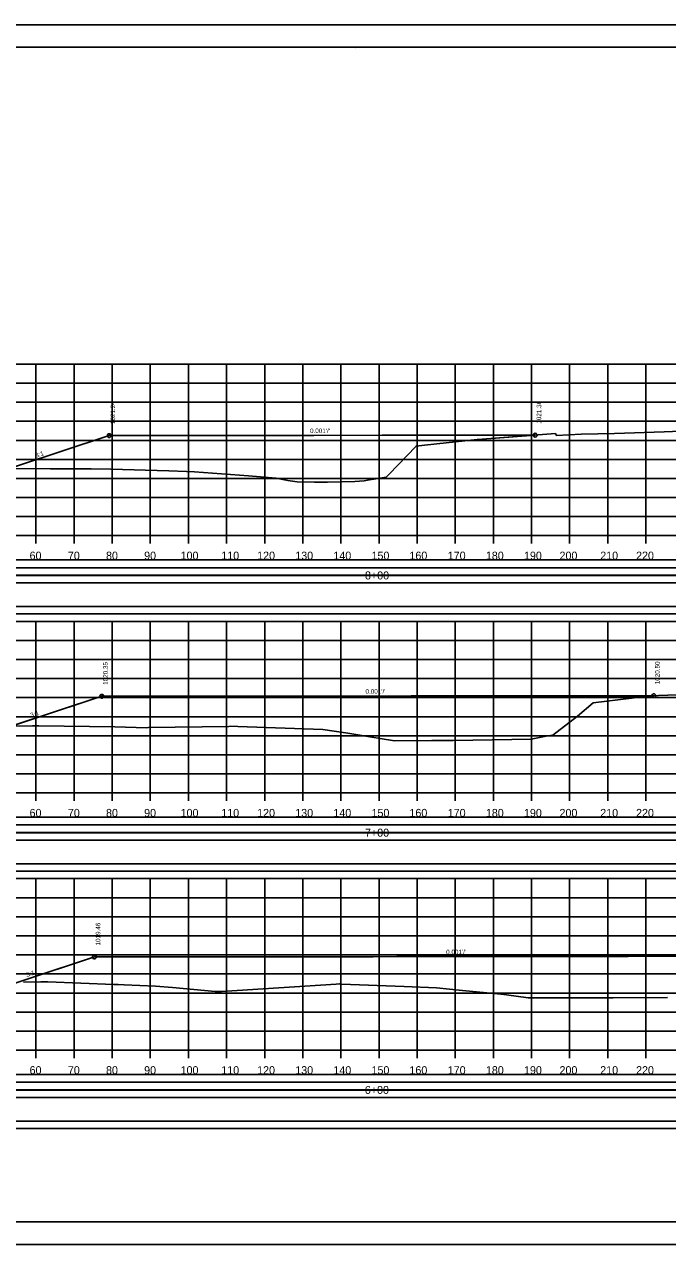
# Model space of a CAD drawing. Extents: x 1370565 to 1374448, y 301010 to 304637.
# Drawn here: x 1374108.6 to 1374277.1, y 301728.1 to 302053 of the extents above; entities that cross this region are included whole.
import ezdxf

# ---------------------------------------------------------------- set-up
doc = ezdxf.new("R2010")
doc.units = 0
for name, color, linetype in [('Default', 7, 'Continuous'), ('R_Axis', 7, 'Continuous'), ('R_Axis Annot', 7, 'Continuous'), ('R_Border', 7, 'Continuous'), ('R_Contours', 7, 'Continuous'), ('R_Drive', 7, 'Continuous'), ('R_Exist Surface', 7, 'Continuous'), ('R_Fin Surface', 7, 'Continuous'), ('R_Grid', 7, 'Continuous'), ('R_No Plot', 7, 'Continuous'), ('R_Xsect Elev', 7, 'Continuous'), ('R_Xsect Slope', 7, 'Continuous')]:
    doc.layers.add(name, color=color, linetype=linetype)

msp = doc.modelspace()

# ---------------------------------------------------------------- linework, layer by layer
at = {"layer": 'Default'}
for points in [[(1373981.44, 301908.59), (1374421.61, 301908.59), (1374421.61, 301912.58), (1373981.44, 301912.58)], [(1373981.44, 301900.36), (1374421.61, 301900.36), (1374421.61, 301908.51), (1373981.44, 301908.51)], [(1373981.44, 301841.09), (1374421.61, 301841.09), (1374421.61, 301845.08), (1373981.44, 301845.08)], [(1373981.44, 301832.86), (1374421.61, 301832.86), (1374421.61, 301841.01), (1373981.44, 301841.01)], [(1373981.44, 301773.59), (1374421.61, 301773.59), (1374421.61, 301777.58), (1373981.44, 301777.58)], [(1373981.44, 301765.36), (1374421.61, 301765.36), (1374421.61, 301773.51), (1373981.44, 301773.51)]]:
    msp.add_lwpolyline(points, close=True, dxfattribs=at)
at = {"layer": 'R_Axis'}
for p, q in [((1373981.52, 301918.96), (1374421.52, 301918.96)), ((1374111.52, 301916.86), (1374111.52, 301918.96)), ((1374121.52, 301916.86), (1374121.52, 301918.96)), ((1374131.52, 301916.86), (1374131.52, 301918.96)), ((1374141.52, 301916.86), (1374141.52, 301918.96)), ((1374151.52, 301916.86), (1374151.52, 301918.96)), ((1374161.52, 301916.86), (1374161.52, 301918.96)), ((1374171.52, 301916.86), (1374171.52, 301918.96)), ((1374181.52, 301916.86), (1374181.52, 301918.96)), ((1374191.52, 301916.86), (1374191.52, 301918.96)), ((1374201.52, 301916.86), (1374201.52, 301918.96)), ((1374211.52, 301916.86), (1374211.52, 301918.96)), ((1374221.52, 301916.86), (1374221.52, 301918.96)), ((1374231.52, 301916.86), (1374231.52, 301918.96)), ((1374241.52, 301916.86), (1374241.52, 301918.96)), ((1374251.52, 301916.86), (1374251.52, 301918.96)), ((1374261.52, 301916.86), (1374261.52, 301918.96)), ((1374271.52, 301916.86), (1374271.52, 301918.96)), ((1373981.52, 301851.46), (1374421.52, 301851.46)), ((1374111.52, 301849.36), (1374111.52, 301851.46)), ((1374121.52, 301849.36), (1374121.52, 301851.46)), ((1374131.52, 301849.36), (1374131.52, 301851.46)), ((1374141.52, 301849.36), (1374141.52, 301851.46)), ((1374151.52, 301849.36), (1374151.52, 301851.46)), ((1374161.52, 301849.36), (1374161.52, 301851.46)), ((1374171.52, 301849.36), (1374171.52, 301851.46)), ((1374181.52, 301849.36), (1374181.52, 301851.46)), ((1374191.52, 301849.36), (1374191.52, 301851.46)), ((1374201.52, 301849.36), (1374201.52, 301851.46)), ((1374211.52, 301849.36), (1374211.52, 301851.46)), ((1374221.52, 301849.36), (1374221.52, 301851.46)), ((1374231.52, 301849.36), (1374231.52, 301851.46)), ((1374241.52, 301849.36), (1374241.52, 301851.46)), ((1374251.52, 301849.36), (1374251.52, 301851.46)), ((1374261.52, 301849.36), (1374261.52, 301851.46)), ((1374271.52, 301849.36), (1374271.52, 301851.46)), ((1373981.52, 301783.96), (1374421.52, 301783.96)), ((1374111.52, 301781.86), (1374111.52, 301783.96)), ((1374121.52, 301781.86), (1374121.52, 301783.96)), ((1374131.52, 301781.86), (1374131.52, 301783.96)), ((1374141.52, 301781.86), (1374141.52, 301783.96)), ((1374151.52, 301781.86), (1374151.52, 301783.96)), ((1374161.52, 301781.86), (1374161.52, 301783.96)), ((1374171.52, 301781.86), (1374171.52, 301783.96)), ((1374181.52, 301781.86), (1374181.52, 301783.96)), ((1374191.52, 301781.86), (1374191.52, 301783.96)), ((1374201.52, 301781.86), (1374201.52, 301783.96)), ((1374211.52, 301781.86), (1374211.52, 301783.96)), ((1374221.52, 301781.86), (1374221.52, 301783.96)), ((1374231.52, 301781.86), (1374231.52, 301783.96)), ((1374241.52, 301781.86), (1374241.52, 301783.96)), ((1374251.52, 301781.86), (1374251.52, 301783.96)), ((1374261.52, 301781.86), (1374261.52, 301783.96)), ((1374271.52, 301781.86), (1374271.52, 301783.96))]:
    msp.add_line(p, q, dxfattribs=at)
at = {"layer": 'R_Border'}
for p, q in [((1373966.52, 302047.15), (1374440.79, 302047.15)), ((1374195.3, 302046.76), (1374195.3, 302046.76)), ((1374195.3, 302046.76), (1374195.3, 302046.76)), ((1374440.79, 301738.96), (1373966.52, 301738.96))]:
    msp.add_line(p, q, dxfattribs=at)
at = {"layer": 'R_Contours'}
msp.add_line((1374105.04, 301868.97), (1374110.61, 301869.03), dxfattribs=at)
for points in [[(1374242.52, 301945.32), (1374202.34, 301945.28), (1374184.44, 301945.26), (1374130.75, 301945.21), (1374104.56, 301936.57)], [(1374104.97, 301936.57), (1374115.33, 301936.47), (1374117.44, 301936.45), (1374118.67, 301936.48), (1374125.98, 301936.53), (1374131.19, 301936.4), (1374146.36, 301935.92), (1374151.02, 301935.78), (1374153.1, 301935.7), (1374167.25, 301934.64), (1374174.54, 301934), (1374177.63, 301933.44), (1374180.05, 301933.11), (1374184.6, 301932.95), (1374188.04, 301932.95), (1374195.19, 301933.18), (1374197.58, 301933.3), (1374198.54, 301933.49), (1374203.4, 301934.32), (1374204.08, 301935.03), (1374211.23, 301942.44), (1374213.48, 301942.72), (1374227.25, 301944.15), (1374227.44, 301944.17), (1374242.52, 301945.32)], [(1374242.52, 301945.32), (1374242.52, 301945.32)], [(1374272.42, 301876.96), (1374233.12, 301876.92), (1374229.92, 301876.92), (1374222.02, 301876.91), (1374221.53, 301876.91), (1374209.98, 301876.9), (1374184.1, 301876.87), (1374173.54, 301876.86), (1374128.8, 301876.81), (1374105.04, 301868.97)], [(1374110.61, 301869.03), (1374111.51, 301869.03), (1374111.71, 301869.02), (1374112.28, 301869.03), (1374132.17, 301868.82), (1374140.62, 301868.57), (1374141.08, 301868.58), (1374162.08, 301868.89), (1374162.48, 301868.96), (1374164.51, 301868.89), (1374186.82, 301868.09), (1374193.35, 301867.11), (1374199.62, 301866.12), (1374201.78, 301865.75), (1374205.61, 301865.09), (1374215.36, 301865.18), (1374220.96, 301865.21), (1374236.36, 301865.49), (1374241.41, 301865.58), (1374245.35, 301866.33), (1374247.14, 301866.65), (1374253.56, 301871.63), (1374257.7, 301875.08), (1374267.75, 301876.31), (1374272.42, 301876.91)], [(1374272.42, 301876.91), (1374272.42, 301876.96)], [(1374317.68, 301808.61), (1374266.85, 301808.56), (1374264.61, 301808.56), (1374254.84, 301808.55), (1374231.88, 301808.53), (1374221.77, 301808.52), (1374217.78, 301808.51), (1374206.15, 301808.5), (1374200.02, 301808.49), (1374182.07, 301808.48), (1374172.35, 301808.47), (1374169.22, 301808.46), (1374168.09, 301808.46), (1374141.64, 301808.44), (1374139.37, 301808.43), (1374126.85, 301808.42), (1374106.89, 301801.84)], [(1374108.29, 301801.84), (1374112.82, 301801.89), (1374114.61, 301801.86), (1374131.97, 301801.19), (1374133.1, 301801.17), (1374134.64, 301801.1), (1374142.87, 301800.77), (1374147.37, 301800.38), (1374158.51, 301799.35), (1374160.17, 301799.32), (1374190.24, 301801.27), (1374191.12, 301801.34), (1374191.31, 301801.33), (1374191.65, 301801.32), (1374208.08, 301800.69), (1374216.59, 301800.35), (1374223.42, 301799.63), (1374233.48, 301798.69), (1374234.97, 301798.48), (1374240.68, 301797.73), (1374243.85, 301797.7), (1374253.75, 301797.7), (1374260.25, 301797.69), (1374262.96, 301797.71), (1374277.22, 301797.77)]]:
    msp.add_lwpolyline(points, dxfattribs=at)
at = {"layer": 'R_Drive'}
for points in [[(1373981.52, 301906.55), (1374421.73, 301906.55), (1374421.73, 301910.55), (1373981.52, 301910.55)], [(1373981.52, 301898.41), (1374421.73, 301898.41), (1374421.73, 301906.55), (1373981.52, 301906.55)], [(1373981.52, 301839.07), (1374421.73, 301839.07), (1374421.73, 301843.06), (1373981.52, 301843.06)], [(1373981.52, 301830.92), (1374421.73, 301830.92), (1374421.73, 301839.07), (1373981.52, 301839.07)], [(1373981.52, 301771.53), (1374421.73, 301771.53), (1374421.73, 301775.53), (1373981.52, 301775.53)], [(1373981.52, 301763.39), (1374421.73, 301763.39), (1374421.73, 301771.53), (1373981.52, 301771.53)]]:
    msp.add_lwpolyline(points, close=True, dxfattribs=at)
at = {"layer": 'R_Exist Surface'}
for points in [[(1374104.97, 301936.57), (1374115.33, 301936.47), (1374117.44, 301936.45), (1374118.67, 301936.48), (1374125.98, 301936.53), (1374131.19, 301936.4), (1374146.36, 301935.92), (1374151.02, 301935.78), (1374153.1, 301935.7), (1374167.25, 301934.64), (1374174.54, 301934), (1374177.63, 301933.44), (1374180.05, 301933.11), (1374184.6, 301932.95), (1374188.04, 301932.95), (1374195.19, 301933.18), (1374197.58, 301933.3), (1374198.54, 301933.49), (1374203.4, 301934.32), (1374204.08, 301935.03), (1374211.23, 301942.44), (1374213.48, 301942.72), (1374227.25, 301944.15), (1374227.44, 301944.17), (1374227.48, 301944.17), (1374247.78, 301945.72), (1374248.05, 301945.24), (1374254.57, 301945.56), (1374263.28, 301945.76), (1374276.28, 301946.22), (1374283, 301946.42)], [(1374095.51, 301868.88), (1374110.61, 301869.03), (1374111.51, 301869.03), (1374111.71, 301869.02), (1374112.28, 301869.03), (1374132.17, 301868.82), (1374140.62, 301868.57), (1374141.08, 301868.58), (1374162.08, 301868.89), (1374162.48, 301868.96), (1374164.51, 301868.89), (1374186.82, 301868.09), (1374193.35, 301867.11), (1374199.62, 301866.12), (1374201.78, 301865.75), (1374205.61, 301865.09), (1374215.36, 301865.18), (1374220.96, 301865.21), (1374236.36, 301865.49), (1374241.41, 301865.58), (1374245.35, 301866.33), (1374247.14, 301866.65), (1374253.56, 301871.63), (1374257.7, 301875.08), (1374267.75, 301876.31), (1374272.42, 301876.91), (1374284.59, 301877.4)], [(1374108.29, 301801.84), (1374112.82, 301801.89), (1374114.61, 301801.86), (1374131.97, 301801.19), (1374133.1, 301801.17), (1374134.64, 301801.1), (1374142.87, 301800.77), (1374147.37, 301800.38), (1374158.51, 301799.35), (1374160.17, 301799.32), (1374190.24, 301801.27), (1374191.12, 301801.34), (1374191.31, 301801.33), (1374191.65, 301801.32), (1374208.08, 301800.69), (1374216.59, 301800.35), (1374223.42, 301799.63), (1374233.48, 301798.69), (1374234.97, 301798.48), (1374240.68, 301797.73), (1374243.85, 301797.7), (1374253.75, 301797.7), (1374260.25, 301797.69), (1374262.96, 301797.71), (1374277.22, 301797.77)]]:
    msp.add_lwpolyline(points, dxfattribs=at)
at = {"layer": 'R_Fin Surface'}
for points in [[(1374006.88, 301935.86), (1374012.46, 301933.07), (1374040.44, 301932.79), (1374046.44, 301929.79), (1374054.44, 301929.79), (1374060.44, 301932.79), (1374061.44, 301932.8), (1374094.14, 301933.12), (1374130.75, 301945.21), (1374184.44, 301945.26), (1374202.34, 301945.28), (1374242.52, 301945.32)], [(1374006.83, 301868.14), (1374012.15, 301865.47), (1374055.75, 301865.04), (1374061.75, 301862.04), (1374069.75, 301862.04), (1374075.75, 301865.04), (1374076.75, 301865.05), (1374093.66, 301865.22), (1374128.8, 301876.81), (1374173.54, 301876.86), (1374184.1, 301876.87), (1374209.98, 301876.9), (1374221.53, 301876.91), (1374222.02, 301876.91), (1374229.92, 301876.92), (1374233.12, 301876.92), (1374273.59, 301876.96)], [(1374093.3, 301797.35), (1374126.85, 301808.42), (1374139.37, 301808.43), (1374141.64, 301808.44), (1374168.09, 301808.46), (1374169.22, 301808.46), (1374172.35, 301808.47), (1374182.07, 301808.48), (1374200.02, 301808.49), (1374206.15, 301808.5), (1374217.78, 301808.51), (1374221.77, 301808.52), (1374231.88, 301808.53), (1374254.84, 301808.55), (1374264.61, 301808.56), (1374264.66, 301808.56), (1374266.85, 301808.56), (1374317.68, 301808.61)]]:
    msp.add_lwpolyline(points, dxfattribs=at)
at = {"layer": 'R_Grid'}
for p, q in [((1373981.52, 301963.96), (1374421.52, 301963.96)), ((1374111.52, 301918.96), (1374111.52, 301963.96)), ((1374121.52, 301918.96), (1374121.52, 301963.96)), ((1374131.52, 301918.96), (1374131.52, 301963.96)), ((1374141.52, 301918.96), (1374141.52, 301963.96)), ((1374151.52, 301918.96), (1374151.52, 301963.96)), ((1374161.52, 301918.96), (1374161.52, 301963.96)), ((1374171.52, 301918.96), (1374171.52, 301963.96)), ((1374181.52, 301918.96), (1374181.52, 301963.96)), ((1374191.52, 301918.96), (1374191.52, 301963.96)), ((1374201.52, 301918.96), (1374201.52, 301963.96)), ((1374211.52, 301918.96), (1374211.52, 301963.96)), ((1374221.52, 301918.96), (1374221.52, 301963.96)), ((1374231.52, 301918.96), (1374231.52, 301963.96)), ((1374241.52, 301918.96), (1374241.52, 301963.96)), ((1374251.52, 301918.96), (1374251.52, 301963.96)), ((1374261.52, 301918.96), (1374261.52, 301963.96)), ((1374271.52, 301918.96), (1374271.52, 301963.96)), ((1373981.52, 301958.96), (1374421.52, 301958.96)), ((1373981.52, 301953.96), (1374421.52, 301953.96)), ((1373981.52, 301948.96), (1374421.52, 301948.96)), ((1373981.52, 301943.96), (1374421.52, 301943.96)), ((1373981.52, 301938.96), (1374421.52, 301938.96)), ((1373981.52, 301933.96), (1374421.52, 301933.96)), ((1373981.52, 301928.96), (1374421.52, 301928.96)), ((1373981.52, 301923.96), (1374421.52, 301923.96)), ((1373981.52, 301918.96), (1374421.52, 301918.96)), ((1373981.52, 301896.46), (1374421.52, 301896.46)), ((1374111.52, 301851.46), (1374111.52, 301896.46)), ((1374121.52, 301851.46), (1374121.52, 301896.46)), ((1374131.52, 301851.46), (1374131.52, 301896.46)), ((1374141.52, 301851.46), (1374141.52, 301896.46)), ((1374151.52, 301851.46), (1374151.52, 301896.46)), ((1374161.52, 301851.46), (1374161.52, 301896.46)), ((1374171.52, 301851.46), (1374171.52, 301896.46)), ((1374181.52, 301851.46), (1374181.52, 301896.46)), ((1374191.52, 301851.46), (1374191.52, 301896.46)), ((1374201.52, 301851.46), (1374201.52, 301896.46)), ((1374211.52, 301851.46), (1374211.52, 301896.46)), ((1374221.52, 301851.46), (1374221.52, 301896.46)), ((1374231.52, 301851.46), (1374231.52, 301896.46)), ((1374241.52, 301851.46), (1374241.52, 301896.46)), ((1374251.52, 301851.46), (1374251.52, 301896.46)), ((1374261.52, 301851.46), (1374261.52, 301896.46)), ((1374271.52, 301851.46), (1374271.52, 301896.46)), ((1373981.52, 301891.46), (1374421.52, 301891.46)), ((1373981.52, 301886.46), (1374421.52, 301886.46)), ((1373981.52, 301881.46), (1374421.52, 301881.46)), ((1373981.52, 301876.46), (1374421.52, 301876.46)), ((1373981.52, 301871.46), (1374421.52, 301871.46)), ((1373981.52, 301866.46), (1374421.52, 301866.46)), ((1373981.52, 301861.46), (1374421.52, 301861.46)), ((1373981.52, 301856.46), (1374421.52, 301856.46)), ((1373981.52, 301851.46), (1374421.52, 301851.46)), ((1373981.52, 301828.96), (1374421.52, 301828.96)), ((1374111.52, 301783.96), (1374111.52, 301828.96)), ((1374121.52, 301783.96), (1374121.52, 301828.96)), ((1374131.52, 301783.96), (1374131.52, 301828.96)), ((1374141.52, 301783.96), (1374141.52, 301828.96)), ((1374151.52, 301783.96), (1374151.52, 301828.96)), ((1374161.52, 301783.96), (1374161.52, 301828.96)), ((1374171.52, 301783.96), (1374171.52, 301828.96)), ((1374181.52, 301783.96), (1374181.52, 301828.96)), ((1374191.52, 301783.96), (1374191.52, 301828.96)), ((1374201.52, 301783.96), (1374201.52, 301828.96)), ((1374211.52, 301783.96), (1374211.52, 301828.96)), ((1374221.52, 301783.96), (1374221.52, 301828.96)), ((1374231.52, 301783.96), (1374231.52, 301828.96)), ((1374241.52, 301783.96), (1374241.52, 301828.96)), ((1374251.52, 301783.96), (1374251.52, 301828.96)), ((1374261.52, 301783.96), (1374261.52, 301828.96)), ((1374271.52, 301783.96), (1374271.52, 301828.96)), ((1373981.52, 301823.96), (1374421.52, 301823.96)), ((1373981.52, 301818.96), (1374421.52, 301818.96)), ((1373981.52, 301813.96), (1374421.52, 301813.96)), ((1373981.52, 301808.96), (1374421.52, 301808.96)), ((1373981.52, 301803.96), (1374421.52, 301803.96)), ((1373981.52, 301798.96), (1374421.52, 301798.96)), ((1373981.52, 301793.96), (1374421.52, 301793.96)), ((1373981.52, 301788.96), (1374421.52, 301788.96)), ((1373981.52, 301783.96), (1374421.52, 301783.96))]:
    msp.add_line(p, q, dxfattribs=at)
at = {"layer": 'R_No Plot'}
for p, q in [((1373947.92, 302053), (1374447.92, 302053)), ((1373947.92, 301733), (1374447.92, 301733)), ((1373947.92, 301732.99), (1374447.92, 301732.99))]:
    msp.add_line(p, q, dxfattribs=at)
for points in [[(1373947.91, 302053), (1374447.92, 302053), (1374447.92, 301732.99), (1373947.91, 301732.99)], [(1374317.4, 302047.15), (1374346.83, 302047.15), (1374346.83, 302032.33), (1374371, 302032.33), (1374405.8, 302032.33), (1374405.98, 301990.1), (1374440.79, 301990.1), (1374440.79, 301738.96), (1373966.52, 301738.96), (1373966.52, 302047.15)], [(1373947.91, 301732.99), (1374447.92, 301732.99), (1374447.92, 301412.98), (1373947.91, 301412.98)]]:
    msp.add_lwpolyline(points, close=True, dxfattribs=at)
for centre in [(1374130.75, 301945.21), (1374242.52, 301945.32), (1374128.8, 301876.81), (1374273.59, 301876.96), (1374126.85, 301808.42)]:
    msp.add_circle(centre, 0.5, dxfattribs=at)

# ---------------------------------------------------------------- texts
at = {"layer": 'R_Axis Annot'}
for s, p in [('60', (1374109.85, 301912.66)), ('70', (1374119.9, 301912.66)), ('80', (1374129.9, 301912.66)), ('90', (1374139.9, 301912.66)), ('100', (1374149.47, 301912.66)), ('110', (1374160.14, 301912.66)), ('120', (1374169.55, 301912.66)), ('130', (1374179.55, 301912.66)), ('140', (1374189.55, 301912.66)), ('150', (1374199.55, 301912.66)), ('160', (1374209.5, 301912.66)), ('170', (1374219.55, 301912.66)), ('180', (1374229.55, 301912.66)), ('190', (1374239.55, 301912.66)), ('200', (1374248.87, 301912.66)), ('210', (1374259.55, 301912.66)), ('220', (1374268.95, 301912.66)), ('8+00', (1374197.84, 301907.47)), ('60', (1374109.85, 301845.16)), ('70', (1374119.9, 301845.16)), ('80', (1374129.9, 301845.16)), ('90', (1374139.9, 301845.16)), ('100', (1374149.47, 301845.16)), ('110', (1374160.14, 301845.16)), ('120', (1374169.55, 301845.16)), ('130', (1374179.55, 301845.16)), ('140', (1374189.55, 301845.16)), ('150', (1374199.55, 301845.16)), ('160', (1374209.5, 301845.16)), ('170', (1374219.55, 301845.16)), ('180', (1374229.55, 301845.16)), ('190', (1374239.55, 301845.16)), ('200', (1374248.87, 301845.16)), ('210', (1374259.55, 301845.16)), ('220', (1374268.95, 301845.16)), ('7+00', (1374197.84, 301839.97)), ('60', (1374109.85, 301777.66)), ('70', (1374119.9, 301777.66)), ('80', (1374129.9, 301777.66)), ('90', (1374139.9, 301777.66)), ('100', (1374149.47, 301777.66)), ('110', (1374160.14, 301777.66)), ('120', (1374169.55, 301777.66)), ('130', (1374179.55, 301777.66)), ('140', (1374189.55, 301777.66)), ('150', (1374199.55, 301777.66)), ('160', (1374209.5, 301777.66)), ('170', (1374219.55, 301777.66)), ('180', (1374229.55, 301777.66)), ('190', (1374239.55, 301777.66)), ('200', (1374248.87, 301777.66)), ('210', (1374259.55, 301777.66)), ('220', (1374268.95, 301777.66)), ('6+00', (1374197.8, 301772.47))]:
    msp.add_text(s, height=2.1, dxfattribs=at).set_placement(p)
at = {"layer": 'R_Xsect Elev'}
for s, p in [('1021.24', (1374132.3, 301948.21)), ('1021.36', (1374244.07, 301948.32)), ('1020.35', (1374130.35, 301879.81)), ('1020.50', (1374275.14, 301879.96)), ('1019.46', (1374128.4, 301811.42))]:
    msp.add_text(s, height=1.2, rotation=90, dxfattribs=at).set_placement(p)
at = {"layer": 'R_Xsect Slope'}
for s, rotation, p in [("0.001'/'", 0.0573, (1374183.41, 301945.86)), ('3:1', 18.2629, (1374111.5, 301939.38)), ("0.001'/'", 0.0573, (1374197.97, 301877.48)), ('3:1', 18.2629, (1374110.28, 301871.23)), ("0.001'/'", 0.0573, (1374219.13, 301809.11)), ('3:1', 18.2629, (1374109.13, 301803.1))]:
    msp.add_text(s, height=1.2, rotation=rotation, dxfattribs=at).set_placement(p)

doc.saveas('drawing.dxf')
